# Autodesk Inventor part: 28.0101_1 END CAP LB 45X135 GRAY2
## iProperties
Created: 2007-01
Part Number: 28.0101_1 END CAP LB 45X135 GRAY2
Document SubType Name: Modeling
Designer: Andy Moles
Material: ABS Plastic
Density: 1.06 g/cm^3
Author: Andy Moles
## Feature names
1. Extrusion1
2. Fillet1
3. Fillet2
4. Extrusion2
